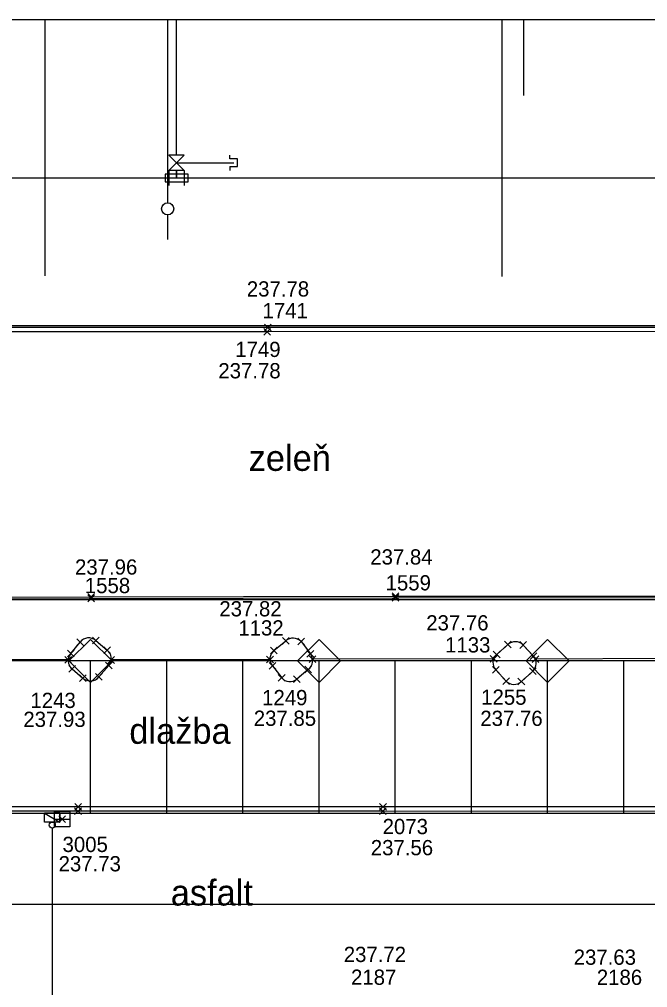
# Model space of a CAD drawing. Extents: x -264165 to -263733, y -1242319 to -1242245.
# Drawn here: x -263891.9 to -263871.28, y -1242276.71 to -1242244.94 of the extents above; entities that cross this region are included whole.
import ezdxf

# ---------------------------------------------------------------- set-up
doc = ezdxf.new("R2010")
doc.units = 0
for name, color, linetype in [('KFA_BOD_CISLO', 7, 'Continuous'), ('KFA_BOD_SYMBOL', 7, 'Continuous'), ('KFA_BOD_VYSKA', 7, 'Continuous'), ('KFA_SO_20-2_OBRUBNIKY_DOLNA_HRANA', 7, 'Continuous'), ('KFA_SO_20-2_OBRUBNIKY_HORNA_HRANA', 7, 'Continuous'), ('KFA_UV_BOD_CISLO', 7, 'Continuous'), ('KFA_UV_BOD_SYMBOL', 7, 'Continuous'), ('KFA_UV_BOD_VYSKA', 7, 'Continuous'), ('POPIS', 7, 'Continuous'), ('PROJEKT_OBRUBNIKY_KOMUNIKACIE', 7, 'Continuous'), ('PROJEKT_TDZ_VODOROVNE', 7, 'Continuous'), ('RAM_NA_TLAC_1-250', 7, 'Continuous'), ('SITUACIA_DSP_2D', 7, 'Continuous'), ('ULICNA_VPUST_POKLOP', 7, 'Continuous')]:
    doc.layers.add(name, color=color, linetype=linetype)

msp = doc.modelspace()

# ---------------------------------------------------------------- linework, layer by layer
at = {"layer": 'KFA_BOD_SYMBOL'}
for p, q in [((-263883.878, -1242255.295), (-263883.657, -1242255.073)), ((-263883.657, -1242255.295), (-263883.878, -1242255.073)), ((-263883.862, -1242255.154), (-263883.641, -1242254.934)), ((-263883.641, -1242255.154), (-263883.862, -1242254.934)), ((-263889.655, -1242263.992), (-263889.433, -1242263.772)), ((-263889.433, -1242263.992), (-263889.655, -1242263.772)), ((-263889.655, -1242264.042), (-263889.433, -1242263.822)), ((-263889.433, -1242264.042), (-263889.655, -1242263.822)), ((-263879.666, -1242263.975), (-263879.445, -1242263.754)), ((-263879.445, -1242263.975), (-263879.666, -1242263.754)), ((-263879.666, -1242264.025), (-263879.445, -1242263.803)), ((-263879.445, -1242264.025), (-263879.666, -1242263.803)), ((-263889.506, -1242265.427), (-263889.285, -1242265.205)), ((-263889.285, -1242265.427), (-263889.506, -1242265.205)), ((-263883.268, -1242265.437), (-263883.046, -1242265.215)), ((-263883.046, -1242265.437), (-263883.268, -1242265.215)), ((-263882.769, -1242265.46), (-263882.549, -1242265.238)), ((-263882.549, -1242265.46), (-263882.769, -1242265.238)), ((-263890.022, -1242265.478), (-263889.801, -1242265.257)), ((-263889.801, -1242265.478), (-263890.022, -1242265.257)), ((-263889.134, -1242265.74), (-263888.913, -1242265.519)), ((-263888.913, -1242265.74), (-263889.134, -1242265.519)), ((-263883.66, -1242265.755), (-263883.438, -1242265.535)), ((-263883.438, -1242265.755), (-263883.66, -1242265.535)), ((-263875.979, -1242265.556), (-263875.758, -1242265.336)), ((-263875.758, -1242265.556), (-263875.979, -1242265.336)), ((-263875.484, -1242265.575), (-263875.263, -1242265.353)), ((-263875.263, -1242265.575), (-263875.484, -1242265.353)), ((-263890.411, -1242266.059), (-263890.19, -1242265.838)), ((-263890.19, -1242266.059), (-263890.411, -1242265.838)), ((-263890.329, -1242265.856), (-263890.108, -1242265.634)), ((-263890.108, -1242265.856), (-263890.329, -1242265.634)), ((-263889, -1242266.065), (-263888.779, -1242265.843)), ((-263888.779, -1242266.065), (-263889, -1242265.843)), ((-263883.79, -1242266.048), (-263883.568, -1242265.826)), ((-263883.568, -1242266.048), (-263883.79, -1242265.826)), ((-263882.464, -1242265.863), (-263882.242, -1242265.643)), ((-263882.242, -1242265.863), (-263882.464, -1242265.643)), ((-263882.391, -1242266.042), (-263882.17, -1242265.822)), ((-263882.17, -1242266.042), (-263882.391, -1242265.822)), ((-263876.448, -1242266.026), (-263876.227, -1242265.806)), ((-263876.227, -1242266.026), (-263876.448, -1242265.806)), ((-263876.349, -1242265.887), (-263876.128, -1242265.667)), ((-263876.128, -1242265.887), (-263876.349, -1242265.667)), ((-263875.138, -1242265.944), (-263874.916, -1242265.722)), ((-263874.916, -1242265.944), (-263875.138, -1242265.722)), ((-263875.079, -1242266.035), (-263874.858, -1242265.815)), ((-263874.858, -1242266.035), (-263875.079, -1242265.815)), ((-263890.283, -1242266.357), (-263890.062, -1242266.137)), ((-263890.062, -1242266.357), (-263890.283, -1242266.137)), ((-263889.074, -1242266.242), (-263888.853, -1242266.022)), ((-263888.853, -1242266.242), (-263889.074, -1242266.022)), ((-263883.708, -1242266.255), (-263883.486, -1242266.034)), ((-263883.486, -1242266.255), (-263883.708, -1242266.034)), ((-263882.539, -1242266.377), (-263882.318, -1242266.157)), ((-263882.318, -1242266.377), (-263882.539, -1242266.157)), ((-263876.373, -1242266.391), (-263876.152, -1242266.171)), ((-263876.152, -1242266.391), (-263876.373, -1242266.171)), ((-263889.93, -1242266.657), (-263889.709, -1242266.437)), ((-263889.709, -1242266.657), (-263889.93, -1242266.437)), ((-263889.403, -1242266.62), (-263889.182, -1242266.4)), ((-263889.182, -1242266.62), (-263889.403, -1242266.4)), ((-263883.405, -1242266.65), (-263883.183, -1242266.43)), ((-263883.183, -1242266.65), (-263883.405, -1242266.43)), ((-263882.909, -1242266.693), (-263882.688, -1242266.471)), ((-263882.688, -1242266.693), (-263882.909, -1242266.471)), ((-263875.165, -1242266.436), (-263874.943, -1242266.215)), ((-263874.943, -1242266.436), (-263875.165, -1242266.215)), ((-263876.035, -1242266.757), (-263875.814, -1242266.535)), ((-263875.814, -1242266.757), (-263876.035, -1242266.535)), ((-263875.539, -1242266.772), (-263875.318, -1242266.551)), ((-263875.318, -1242266.772), (-263875.539, -1242266.551)), ((-263890.089, -1242271.029), (-263889.867, -1242270.809)), ((-263889.867, -1242271.029), (-263890.089, -1242270.809)), ((-263890.084, -1242270.887), (-263889.862, -1242270.666)), ((-263889.862, -1242270.887), (-263890.084, -1242270.666)), ((-263880.082, -1242271.024), (-263879.861, -1242270.802)), ((-263879.861, -1242271.024), (-263880.082, -1242270.802)), ((-263880.079, -1242270.88), (-263879.857, -1242270.66)), ((-263879.857, -1242270.88), (-263880.079, -1242270.66))]:
    msp.add_line(p, q, dxfattribs=at)
at = {"layer": 'KFA_SO_20-2_OBRUBNIKY_DOLNA_HRANA'}
for points in [[(-263870.27, -1242270.923), (-263879.971, -1242270.913), (-263889.978, -1242270.919), (-263899.995, -1242270.919), (-263908.997, -1242270.923), (-263917.4, -1242270.885)], [(-263870.268, -1242270.778), (-263879.968, -1242270.77), (-263889.973, -1242270.776), (-263899.989, -1242270.776), (-263908.993, -1242270.778), (-263917.158, -1242270.747)]]:
    msp.add_lwpolyline(points, dxfattribs=at)
at = {"layer": 'KFA_SO_20-2_OBRUBNIKY_HORNA_HRANA'}
for p, q in [((-263890.219, -1242265.745), (-263889.911, -1242265.367)), ((-263889.395, -1242265.316), (-263889.024, -1242265.629)), ((-263883.549, -1242265.645), (-263883.157, -1242265.326)), ((-263882.659, -1242265.349), (-263882.353, -1242265.753)), ((-263876.238, -1242265.777), (-263875.868, -1242265.446)), ((-263875.373, -1242265.464), (-263875.027, -1242265.833)), ((-263890.301, -1242265.948), (-263896.366, -1242265.948)), ((-263888.964, -1242266.132), (-263889.292, -1242266.51)), ((-263883.679, -1242265.937), (-263888.889, -1242265.954)), ((-263883.597, -1242266.144), (-263883.294, -1242266.54)), ((-263876.338, -1242265.916), (-263882.28, -1242265.932)), ((-263868.367, -1242265.903), (-263874.969, -1242265.925)), ((-263890.172, -1242266.247), (-263889.819, -1242266.547)), ((-263882.428, -1242266.267), (-263882.798, -1242266.582)), ((-263876.263, -1242266.281), (-263875.925, -1242266.646)), ((-263875.428, -1242266.661), (-263875.054, -1242266.325))]:
    msp.add_line(p, q, dxfattribs=at)
for points in [[(-263854.465, -1242263.815), (-263854.458, -1242255.02), (-263866.883, -1242255.042), (-263883.752, -1242255.044), (-263902.029, -1242255.047), (-263909.175, -1242255.048), (-263919.956, -1242255.04), (-263920.002, -1242255.04)], [(-263854.511, -1242263.815), (-263854.507, -1242255.162), (-263866.835, -1242255.182), (-263883.768, -1242255.184), (-263902.097, -1242255.191), (-263916.995, -1242263.915)], [(-263909.527, -1242263.897), (-263899.537, -1242263.895), (-263889.544, -1242263.882), (-263879.556, -1242263.864), (-263869.563, -1242263.857), (-263859.593, -1242263.827), (-263846.594, -1242263.797), (-263839.607, -1242263.784)], [(-263909.527, -1242263.947), (-263899.537, -1242263.945), (-263889.544, -1242263.932), (-263879.556, -1242263.914), (-263869.563, -1242263.907), (-263859.593, -1242263.877), (-263846.594, -1242263.847), (-263839.607, -1242263.834)]]:
    msp.add_lwpolyline(points, dxfattribs=at)
for centre, major_axis, ratio, start_param, end_param in [((-263889.629, -1242265.589), (-0.359, 0.015), 0.99962, 4.0469, 5.65862), ((-263882.92, -1242265.59), (-0.278, -0.22), 0.999925, 3.218386, 4.777038), ((-263875.63, -1242265.712), (-0.318, -0.162), 0.999448, 3.43782, 4.971809), ((-263889.948, -1242265.973), (0.164, -0.314), 0.999876, 3.531907, 5.116886), ((-263889.243, -1242265.91), (0.067, 0.35), 0.999472, 4.230562, 5.811287), ((-263883.329, -1242265.918), (0.128, -0.327), 0.999209, 3.448529, 5.039278), ((-263882.638, -1242265.974), (0.101, 0.346), 0.999903, 4.047569, 5.654739), ((-263876.02, -1242266.04), (-0.017, -0.341), 0.999959, 3.881809, 5.542969), ((-263875.293, -1242266.065), (0.295, 0.193), 0.999971, 4.876617, 6.421987), ((-263889.573, -1242266.278), (0.354, 0.088), 0.999033, 3.729542, 5.349023), ((-263883.025, -1242266.316), (0.274, -0.218), 0.999835, 4.508507, 6.089955), ((-263875.669, -1242266.402), (0.346, -0.075), 0.999012, 4.116388, 5.672493)]:
    msp.add_ellipse(centre, major_axis=major_axis, ratio=ratio, start_param=start_param, end_param=end_param, dxfattribs=at)
at = {"layer": 'KFA_UV_BOD_SYMBOL'}
for p, q in [((-263890.606, -1242271.289), (-263890.384, -1242271.069)), ((-263890.384, -1242271.289), (-263890.606, -1242271.069))]:
    msp.add_line(p, q, dxfattribs=at)
at = {"layer": 'PROJEKT_OBRUBNIKY_KOMUNIKACIE'}
for p, q in [((-263807.068, -1242265.987), (-263917.08, -1242265.983)), ((-263917.578, -1242270.983), (-263807.068, -1242270.982))]:
    msp.add_line(p, q, dxfattribs=at)
for points in [[(-263854.468, -1242263.985), (-263917.08, -1242263.982), (-263901.868, -1242254.982), (-263854.468, -1242254.985), (-263854.468, -1242263.985)], [(-263889.568, -1242265.279), (-263888.861, -1242265.986), (-263889.568, -1242266.694), (-263890.275, -1242265.986), (-263889.568, -1242265.279)], [(-263882.068, -1242265.279), (-263881.361, -1242265.986), (-263882.068, -1242266.694), (-263882.775, -1242265.986), (-263882.068, -1242265.279)], [(-263874.568, -1242265.279), (-263873.861, -1242265.986), (-263874.568, -1242266.694), (-263875.275, -1242265.986), (-263874.568, -1242265.279)]]:
    msp.add_lwpolyline(points, dxfattribs=at)
at = {"layer": 'PROJEKT_TDZ_VODOROVNE'}
for p, q in [((-263889.568, -1242270.982), (-263889.568, -1242265.982)), ((-263887.068, -1242270.982), (-263887.068, -1242265.982)), ((-263884.568, -1242270.982), (-263884.568, -1242265.982)), ((-263882.068, -1242270.982), (-263882.068, -1242265.982)), ((-263879.568, -1242270.982), (-263879.568, -1242265.982)), ((-263877.068, -1242270.982), (-263877.068, -1242265.982)), ((-263874.568, -1242270.982), (-263874.568, -1242265.982)), ((-263872.068, -1242270.982), (-263872.068, -1242265.982)), ((-263817.068, -1242273.982), (-263917.477, -1242273.982))]:
    msp.add_line(p, q, dxfattribs=at)
at = {"layer": 'RAM_NA_TLAC_1-250'}
msp.add_line((-263875.363, -1242244.935), (-263875.363, -1242247.435), dxfattribs=at)
msp.add_lwpolyline([(-264165.363, -1242244.935), (-263732.863, -1242244.935), (-263732.863, -1242319.185), (-264165.363, -1242319.185)], close=True, dxfattribs=at)
at = {"layer": 'SITUACIA_DSP_2D'}
for p, q in [((-263891.068, -1242244.935), (-263891.068, -1242253.353)), ((-263887.043, -1242244.935), (-263887.043, -1242250.954)), ((-263886.743, -1242249.39), (-263886.743, -1242244.935)), ((-263876.068, -1242244.935), (-263876.068, -1242253.37)), ((-263886.493, -1242249.39), (-263886.993, -1242249.39)), ((-263886.993, -1242249.89), (-263886.493, -1242249.39)), ((-263886.993, -1242249.39), (-263886.493, -1242249.89)), ((-263886.743, -1242249.64), (-263884.868, -1242249.64)), ((-263884.993, -1242249.515), (-263884.993, -1242249.39)), ((-263884.743, -1242249.515), (-263884.993, -1242249.515)), ((-263884.743, -1242249.765), (-263884.743, -1242249.515)), ((-263886.493, -1242249.89), (-263886.993, -1242249.89)), ((-263886.993, -1242249.89), (-263886.993, -1242250.39)), ((-263886.743, -1242250.14), (-263886.743, -1242249.89)), ((-263886.743, -1242249.89), (-263886.743, -1242250.14)), ((-263886.493, -1242249.89), (-263886.493, -1242250.39)), ((-263884.993, -1242249.765), (-263884.993, -1242249.89)), ((-263884.993, -1242249.765), (-263884.743, -1242249.765)), ((-263924.143, -1242250.14), (-263788.143, -1242250.14)), ((-263886.368, -1242250.015), (-263887.118, -1242250.015)), ((-263887.118, -1242250.015), (-263887.118, -1242250.265)), ((-263887.118, -1242250.265), (-263886.368, -1242250.265)), ((-263886.368, -1242250.265), (-263886.368, -1242250.015)), ((-263887.043, -1242251.353), (-263887.043, -1242252.153)), ((-263891.074, -1242270.983), (-263890.574, -1242270.983)), ((-263891.074, -1242271.273), (-263891.074, -1242270.983)), ((-263891.074, -1242270.983), (-263890.574, -1242271.273)), ((-263891.074, -1242270.983), (-263890.574, -1242271.273)), ((-263890.574, -1242270.983), (-263891.074, -1242270.983)), ((-263890.574, -1242271.273), (-263891.074, -1242271.273)), ((-263890.574, -1242270.983), (-263890.574, -1242271.273)), ((-263890.574, -1242271.273), (-263890.574, -1242270.983)), ((-263890.824, -1242271.473), (-263890.824, -1242283.187))]:
    msp.add_line(p, q, dxfattribs=at)
msp.add_lwpolyline([(-263854.468, -1242263.985), (-263917.08, -1242263.982), (-263901.868, -1242254.982), (-263854.468, -1242254.985), (-263854.468, -1242263.985)], dxfattribs=at)
for points in [[(-263889.568, -1242265.279), (-263888.861, -1242265.986), (-263889.568, -1242266.693), (-263890.275, -1242265.986)], [(-263882.068, -1242265.279), (-263881.361, -1242265.986), (-263882.068, -1242266.693), (-263882.775, -1242265.986)], [(-263874.568, -1242265.279), (-263873.861, -1242265.986), (-263874.568, -1242266.693), (-263875.275, -1242265.986)]]:
    msp.add_lwpolyline(points, close=True, dxfattribs=at)
for centre, radius in [((-263887.036, -1242251.153), 0.2), ((-263890.824, -1242271.373), 0.1)]:
    msp.add_circle(centre, radius, dxfattribs=at)
at = {"layer": 'ULICNA_VPUST_POKLOP'}
msp.add_line((-263890.495, -1242271.179), (-263890.495, -1242271.179), dxfattribs=at)
msp.add_lwpolyline([(-263890.745, -1242271.179), (-263890.745, -1242270.929), (-263890.245, -1242270.929), (-263890.245, -1242271.429), (-263890.745, -1242271.429), (-263890.745, -1242271.179), (-263890.245, -1242271.179)], dxfattribs=at)

# ---------------------------------------------------------------- texts
at = {"layer": 'KFA_BOD_CISLO'}
for s, p in [('1741', (-263883.923, -1242254.74)), ('1749', (-263884.818, -1242256.013)), ('1558', (-263889.755, -1242263.762)), ('1559', (-263879.884, -1242263.672)), ('1132', (-263884.718, -1242265.152)), ('1133', (-263877.932, -1242265.709)), ('1243', (-263891.54, -1242267.53)), ('1249', (-263883.936, -1242267.439)), ('1255', (-263876.747, -1242267.424)), ('2073', (-263879.981, -1242271.669)), ('2187', (-263881.019, -1242276.613)), ('2186', (-263872.952, -1242276.616))]:
    msp.add_text(s, height=0.5, dxfattribs=at).set_placement(p)
at = {"layer": 'KFA_BOD_VYSKA'}
for s, p in [('237.78', (-263884.439, -1242254.03)), ('237.78', (-263885.373, -1242256.714)), ('237.84', (-263880.387, -1242262.823)), ('237.96', (-263890.077, -1242263.154)), ('237.82', (-263885.341, -1242264.524)), ('237.76', (-263878.551, -1242264.986)), ('237.93', (-263891.773, -1242268.152)), ('237.85', (-263884.21, -1242268.116)), ('237.76', (-263876.775, -1242268.119)), ('237.56', (-263880.37, -1242272.362)), ('237.72', (-263881.257, -1242275.865)), ('237.63', (-263873.711, -1242275.956))]:
    msp.add_text(s, height=0.5, dxfattribs=at).set_placement(p)
at = {"layer": 'KFA_UV_BOD_CISLO'}
msp.add_text('3005', height=0.5, dxfattribs=at).set_placement((-263890.486, -1242272.256))
at = {"layer": 'KFA_UV_BOD_VYSKA'}
msp.add_text('237.73', height=0.5, dxfattribs=at).set_placement((-263890.616, -1242272.89))
at = {"layer": 'POPIS'}
for s, p in [('zeleň', (-263884.377, -1242259.75)), ('dlažba', (-263888.294, -1242268.705)), ('asfalt', (-263886.934, -1242274.011))]:
    msp.add_text(s, height=0.8438, dxfattribs=at).set_placement(p)

doc.saveas('drawing.dxf')
